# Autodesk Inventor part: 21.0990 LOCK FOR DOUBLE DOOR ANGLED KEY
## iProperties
Created: 2007-03
Part Number: 21.0990 LOCK FOR DOUBLE DOOR ANGLED KEY
Material: Steel
Document SubType Name: Modeling
Designer: Andy Moles
Density: 7.85 g/cm^3
Author: Andy Moles
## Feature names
1. Base1
